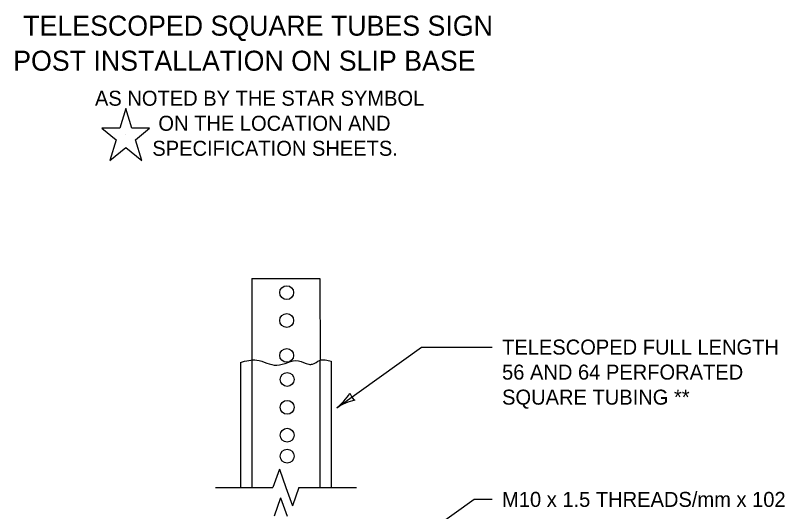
# Model space of a CAD drawing. Extents: x 49940 to 50043, y 49986 to 50011.
# Drawn here: x 50026.993 to 50030.065, y 49994.515 to 49996.498 of the extents above; entities that cross this region are included whole.
import ezdxf

# ---------------------------------------------------------------- set-up
doc = ezdxf.new("R2010")
doc.units = 0
for name, color, linetype in [('Level 1', 7, 'Continuous'), ('Level 2', 7, 'Continuous'), ('Level 3', 7, 'Continuous'), ('Level 4', 7, 'Continuous'), ('Level 6', 7, 'Continuous')]:
    doc.layers.add(name, color=color, linetype=linetype)

msp = doc.modelspace()

# ---------------------------------------------------------------- linework, layer by layer
at = {"layer": 'Level 1'}
msp.add_line((50027.9367, 49995.4471), (50028.2092, 49995.4471), dxfattribs=at)
for points in [[(50027.9367, 49995.4471), (50027.9367, 49995.1177)], [(50028.2092, 49995.4471), (50028.2093, 49995.1192)], [(50027.8913, 49995.1122), (50027.8915, 49994.6113)], [(50028.2546, 49994.6114), (50028.2546, 49995.1163)]]:
    msp.add_lwpolyline(points, dxfattribs=at)
for centre in [(50028.0763, 49995.39), (50028.0763, 49995.39), (50028.0763, 49995.2785), (50028.0763, 49995.1392), (50028.0779, 49995.0432), (50028.0779, 49995.0432), (50028.0779, 49994.9317), (50028.0779, 49994.9317), (50028.0779, 49994.8201), (50028.0779, 49994.7363)]:
    msp.add_circle(centre, 0.0277, dxfattribs=at)
msp.add_spline([(50027.892, 49995.1114), (50027.9568, 49995.1205), (50028.0365, 49995.1), (50028.1237, 49995.1175), (50028.1648, 49995.1036), (50028.1791, 49995.1042), (50028.2078, 49995.1193), (50028.2545, 49995.1163)], degree=3, dxfattribs=at)
at = {"layer": 'Level 2'}
for p, q in [((50027.4335, 49996.1257), (50027.4097, 49996.0474)), ((50027.4575, 49996.0472), (50027.4335, 49996.1257)), ((50027.3385, 49996.0473), (50027.3953, 49996.0007)), ((50027.4098, 49996.0473), (50027.3385, 49996.0473)), ((50027.5287, 49996.0473), (50027.4575, 49996.0473)), ((50027.4719, 49996.0007), (50027.5287, 49996.0473)), ((50027.4335, 49996.0214), (50027.4335, 49996.0214)), ((50027.3953, 49996.0007), (50027.37, 49995.9173)), ((50027.4971, 49995.9173), (50027.4719, 49996.0007)), ((50027.37, 49995.9173), (50027.4336, 49995.9694)), ((50027.4336, 49995.9694), (50027.4971, 49995.9173))]:
    msp.add_line(p, q, dxfattribs=at)
at = {"layer": 'Level 3'}
for p, q in [((50028.2766, 49994.9294), (50028.6151, 49995.1724)), ((50028.6151, 49995.1724), (50028.8964, 49995.1724)), ((50028.8246, 49994.5638), (50028.3946, 49994.2551)), ((50028.8964, 49994.5638), (50028.8246, 49994.5638))]:
    msp.add_line(p, q, dxfattribs=at)
for centre, radius, start, end in [((50028.1315, 49995.1121), 0.233, 308.5009, 327.7507), ((50028.3807, 49995.0045), 0.0548, 197.8124, 233.5347), ((50028.3987, 49994.744), 0.2223, 103.1296, 123.3131)]:
    msp.add_arc(centre, radius, start, end, dxfattribs=at)
at = {"layer": 'Level 4'}
for points in [[(50027.9367, 49995.1177), (50027.9369, 49994.6113)], [(50028.2093, 49994.6114), (50028.2093, 49995.1192)]]:
    msp.add_lwpolyline(points, dxfattribs=at)
at = {"layer": 'Level 6'}
for p, q in [((50028.0471, 49994.6844), (50028.0212, 49994.6113)), ((50028.0471, 49994.6844), (50028.073, 49994.6113)), ((50027.7916, 49994.6113), (50028.0212, 49994.6113)), ((50028.073, 49994.6113), (50028.0989, 49994.5382)), ((50028.1248, 49994.6113), (50028.0989, 49994.5382)), ((50028.1248, 49994.6114), (50028.3545, 49994.6114)), ((50028.052, 49994.5697), (50028.0261, 49994.4966)), ((50028.052, 49994.5697), (50028.0779, 49994.4966))]:
    msp.add_line(p, q, dxfattribs=at)

# ---------------------------------------------------------------- texts
at = {"layer": 'Level 2'}
for s, height, p in [('TELESCOPED SQUARE TUBES SIGN', 0.0799, (50027.0238, 49996.4167)), ('POST INSTALLATION ON SLIP BASE', 0.0799, (50026.9839, 49996.2767)), ('AS NOTED BY THE STAR SYMBOL', 0.06, (50027.3105, 49996.1367)), ('ON THE LOCATION AND', 0.06, (50027.5637, 49996.0367)), (' SPECIFICATION SHEETS.', 0.06, (50027.5173, 49995.9367)), ('TELESCOPED FULL LENGTH', 0.06, (50028.9364, 49995.1424)), ('56 AND 64 PERFORATED', 0.06, (50028.9364, 49995.0424)), ('SQUARE TUBING **', 0.06, (50028.9364, 49994.9424)), ('M10 x 1.5 THREADS/mm x 102', 0.06, (50028.9364, 49994.5338))]:
    msp.add_text(s, height=height, dxfattribs=at).set_placement(p)

doc.saveas('drawing.dxf')
